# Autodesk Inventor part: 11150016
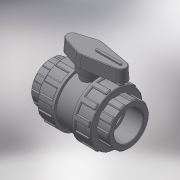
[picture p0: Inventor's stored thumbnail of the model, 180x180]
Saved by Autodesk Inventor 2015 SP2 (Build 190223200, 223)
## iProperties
Created: 2017-11
Part Number: 11150016
Material: Generic
Description: PLASSON 2/NUT VALVE CEM. PVC 16
Document SubType Name: Modeling
Designer: KIM
Density: 1 g/cm^3
Appearance: Default
Author: KIM
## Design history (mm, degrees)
derived "111500.ipt"
feature "Solid1::111500.ipt"
tag "TaggingFeature1"
body "Solid1"
other parameters: "d0" = 71, "d1" = 16, "d2" = 45, "d3" = 14, "d4" = 12.8, "d5" = 9.8, "d7" = 22.4, "d8" = 40.5, "d13" = 0.48, "d23" = 14, "d24" = 43.2, "d25" = 0.32, "d26" = 0.48, "d27" = 6.75, "d28" = 3.375, "d29" = 10.5, "d30" = 0, "d35" = 0.48, "d39" = 22.5, "d45" = 360 deg, "d47" = 0.32, "d50" = 24.75, "d51" = 13.5, "d53" = 0, "d55" = 3.2, "d56" = 1.6, "d57" = 9.8, "d58" = 0, "d59" = 0.48, "d61" = 360 deg, "d63" = 18, "d64" = 45, "d66" = 65, "d68" = 9, "d69" = 19.5, "d70" = 11.25, "d71" = 3 deg, "d73" = 0.9, "d74" = 26, "d75" = 1.35, "d76" = 0, "d77" = 0.32, "d_" = 16, "l_" = 14, "H_" = 71, "K_" = 45, "F_" = 45, "J_" = 65, "d67" = 18, "d72" = 4.5
